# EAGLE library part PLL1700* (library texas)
MULTI-CLOCK GENERATOR GENERATED AUDIO SYSTEM CLOCK Phase Lock Loop (PLL).
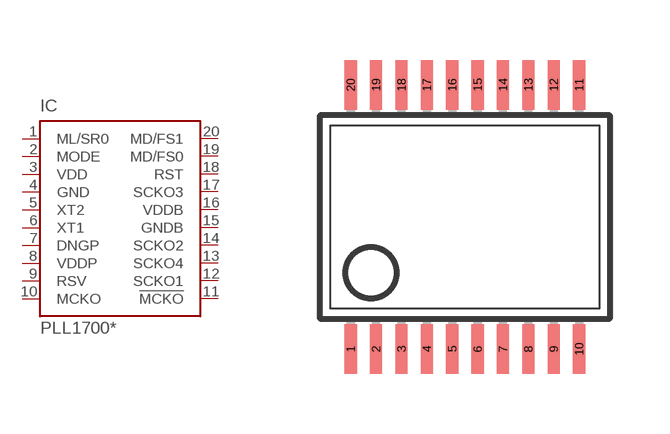
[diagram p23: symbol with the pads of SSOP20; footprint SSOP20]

Designator prefix IC

## PLL1700E (MF: TEXAS INSTRUMENT CONNECTORS; MPN: PLL1700E; OC_FARNELL: unknown; OC_NEWARK: 36K3452)  [SSOP20]
1  ML/SR0  in
2  MODE  in
3  VDD  in
4  GND  pwr
5  XT2  in
6  XT1  in
7  DNGP  pwr
8  VDDP  pwr
9  RSV  pas
10  MCKO  out
11  !MCKO  out
12  SCKO1  out
13  SCKO4  out
14  SCKO2  out
15  GNDB  pwr
16  VDDB  pwr
17  SCKO3  out
18  RST  in
19  MD/FS0  in
20  MD/FS1  in

## Footprint SSOP20 (pad centres in mm)
Small Shrink Outline Package
smd 0.305 x 1.245: 1 -2.857,-3.302; 2 -2.222,-3.302; 3 -1.587,-3.302; 4 -0.952,-3.302; 5 -0.317,-3.302; 6 0.318,-3.302; 7 0.953,-3.302; 8 1.588,-3.302; 9 2.223,-3.302; 10 2.858,-3.302; 11 2.858,3.302; 12 2.223,3.302; 13 1.588,3.302; 14 0.953,3.302; 15 0.318,3.302; 16 -0.317,3.302; 17 -0.952,3.302; 18 -1.587,3.302; 19 -2.222,3.302; 20 -2.857,3.302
